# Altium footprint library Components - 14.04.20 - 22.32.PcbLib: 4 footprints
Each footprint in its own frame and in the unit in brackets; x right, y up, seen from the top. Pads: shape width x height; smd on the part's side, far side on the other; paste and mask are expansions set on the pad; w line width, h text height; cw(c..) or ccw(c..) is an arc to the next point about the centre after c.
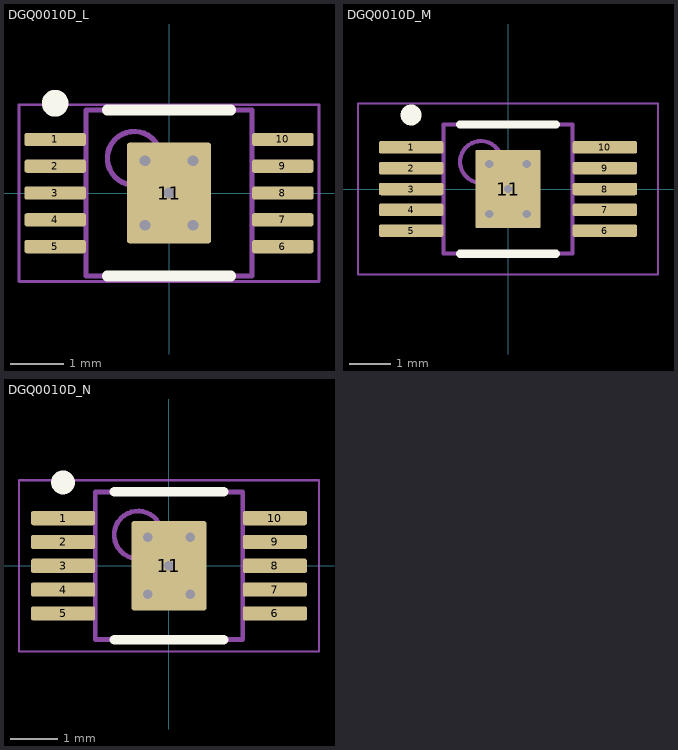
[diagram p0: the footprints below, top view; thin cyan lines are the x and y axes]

## DGQ0010D_L [mm] "TSOP, 10-Leads, Body 3.1x3.1mm, Pitch 0.5mm, Thermal Pad 1.88x1.57mm, IPC High Density"
height 1.1
pads (11):
  rrect40% 1.15x0.25 smd: 1(-2.125,1) 2(-2.125,0.5) 3(-2.125,0) 4(-2.125,-0.5) 5(-2.125,-1) 6(2.125,-1) 7(2.125,-0.5) 8(2.125,0) 9(2.125,0.5) 10(2.125,1)
  rrect6% 1.57x1.88 smd: 11(0,0)
via -0.45,0.6 diameter 0.5 hole 0.2
via -0.45,-0.6 diameter 0.5 hole 0.2
via 0.45,-0.6 diameter 0.5 hole 0.2
via 0.45,0.6 diameter 0.5 hole 0.2
via 0,0 diameter 0.5 hole 0.2
Top Overlay:
  circle w0.25: c-2.125,1.675 r0.125
  lines w0.2: -1.15,-1.55 1.15,-1.55 ; -1.15,1.55 1.15,1.55
Mechanical 1:
  text ".Designator" at -1.397,-0.254 h0.7
Mechanical 13:
  circle w0.1: c-0.65,0.65 r0.5
  lines w0.1: -1.55,-1.55 1.55,-1.55 1.55,1.55 -1.55,1.55 -1.55,-1.55
Mechanical 15:
  lines w0.05: -2.8,-1.65 2.8,-1.65 2.8,1.65 -2.8,1.65 -2.8,-1.65
  lines w0.1: -0.5,0 0.5,0 ; 0,-0.5 0,0.5
3D body "DGQ0010.stp": height 0.94, standoff -0.02, extent -2.451,-1.499 2.451,1.499

## DGQ0010D_M [mm] "TSOP, 10-Leads, Body 3.1x3.1mm, Pitch 0.5mm, Thermal Pad 1.88x1.57mm, IPC Low Density"
height 1.1
pads (11):
  rrect33% 1.55x0.3 smd: 1(-2.325,1) 2(-2.325,0.5) 3(-2.325,0) 4(-2.325,-0.5) 5(-2.325,-1) 6(2.325,-1) 7(2.325,-0.5) 8(2.325,0) 9(2.325,0.5) 10(2.325,1)
  rrect6% 1.57x1.88 smd: 11(0,0)
via -0.45,0.6 diameter 0.5 hole 0.2
via -0.45,-0.6 diameter 0.5 hole 0.2
via 0.45,-0.6 diameter 0.5 hole 0.2
via 0.45,0.6 diameter 0.5 hole 0.2
via 0,0 diameter 0.5 hole 0.2
Top Overlay:
  circle w0.25: c-2.325,1.775 r0.125
  lines w0.2: -1.15,-1.55 1.15,-1.55 ; -1.15,1.55 1.15,1.55
Mechanical 1:
  text ".Designator" at -1.397,-0.254 h0.7
Mechanical 13:
  circle w0.1: c-0.65,0.65 r0.5
  lines w0.1: -1.55,-1.55 1.55,-1.55 1.55,1.55 -1.55,1.55 -1.55,-1.55
Mechanical 15:
  lines w0.05: -3.6,-2.05 3.6,-2.05 3.6,2.05 -3.6,2.05 -3.6,-2.05
  lines w0.1: -0.5,0 0.5,0 ; 0,-0.5 0,0.5
3D body "DGQ0010.stp": height 0.94, standoff -0.02, extent -2.451,-1.499 2.451,1.499

## DGQ0010D_N [mm] "TSOP, 10-Leads, Body 3.1x3.1mm, Pitch 0.5mm, Thermal Pad 1.88x1.57mm, IPC Medium Density"
height 1.1
pads (11):
  rrect33% 1.35x0.3 smd: 1(-2.225,1) 2(-2.225,0.5) 3(-2.225,0) 4(-2.225,-0.5) 5(-2.225,-1) 6(2.225,-1) 7(2.225,-0.5) 8(2.225,0) 9(2.225,0.5) 10(2.225,1)
  rrect6% 1.57x1.88 smd: 11(0,0)
via -0.45,0.6 diameter 0.5 hole 0.2
via -0.45,-0.6 diameter 0.5 hole 0.2
via 0.45,-0.6 diameter 0.5 hole 0.2
via 0.45,0.6 diameter 0.5 hole 0.2
via 0,0 diameter 0.5 hole 0.2
Top Overlay:
  circle w0.25: c-2.225,1.75 r0.125
  lines w0.2: -1.15,-1.55 1.15,-1.55 ; -1.15,1.55 1.15,1.55
Mechanical 1:
  text ".Designator" at -1.397,-0.254 h0.7
Mechanical 13:
  circle w0.1: c-0.65,0.65 r0.5
  lines w0.1: -1.55,-1.55 -1.55,1.55 1.55,1.55 1.55,-1.55 -1.55,-1.55
Mechanical 15:
  lines w0.05: -3.15,-1.8 -3.15,1.8 3.15,1.8 3.15,-1.8 -3.15,-1.8
  lines w0.1: -0.5,0 0.5,0 ; 0,-0.5 0,0.5
3D body "DGQ0010.stp": height 0.94, standoff -0.02, extent -2.451,-1.499 2.451,1.499

## PCBComponent_1 [mm]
